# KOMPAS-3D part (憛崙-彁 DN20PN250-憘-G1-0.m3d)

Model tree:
1. Объединить компоненты:1  (labels: СЕНС-ПР DN20PN250-G1-0)
2. Эскиз:1
3. Операция выдавливания:1
     Расстояние 1 = 14
4. Фаска:1
     Угол = 45; Длина 1 = 2; Длина 2 = 2

Referenced files in D:\Савин\!СЕНСОР\3D для заказчика\!Новый перечень\СЕНС-ПР\5. СЕНС-ПР-PN250\DN20\: СЕНС-ПР DN20PN250-G1-0.a3d
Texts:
  СЕНС-ПР DN20PN250-СВ-G1-0
  ООО НПП Сенсор
  СЕНС-ПР DN20PN250-G1-0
